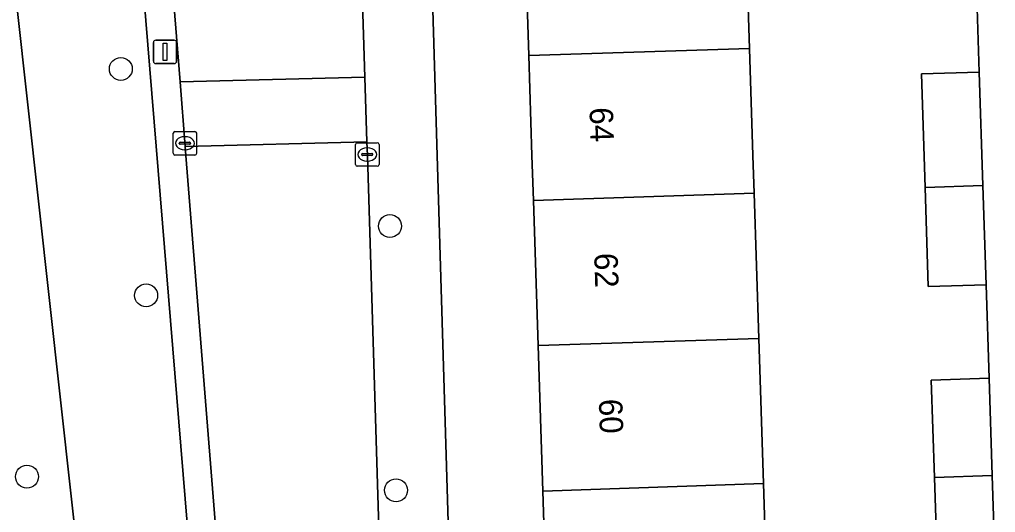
# Model space of a CAD drawing. Extents: x 161248 to 161848, y 384871 to 385383.
# Drawn here: x 161640.06 to 161681.73, y 385234.77 to 385255.81 of the extents above; entities that cross this region are included whole.
import ezdxf

# ---------------------------------------------------------------- set-up
doc = ezdxf.new("R2010")
doc.units = 0
for name, color, linetype in [('IMGEO_Boom', 7, 'Continuous'), ('IMGEO_Erf', 7, 'Continuous'), ('IMGEO_Groenvoorziening', 7, 'Continuous'), ('IMGEO_Hek', 7, 'Continuous'), ('IMGEO_Kolk', 7, 'Continuous'), ('IMGEO_Lichtmast', 7, 'Continuous'), ('IMGEO_Pand', 7, 'Continuous'), ('IMGEO_Pand_nummerreeks', 7, 'Continuous'), ('IMGEO_Rijbaan_lokaal_open', 7, 'Continuous'), ('IMGEO_Voetpad_open', 7, 'Continuous')]:
    doc.layers.add(name, color=color, linetype=linetype)

msp = doc.modelspace()

# ---------------------------------------------------------------- linework, layer by layer
at = {"layer": 'IMGEO_Boom'}
for centre in [(161644.385, 385253.703), (161655.874, 385246.993), (161645.466, 385244.033), (161640.378, 385236.297), (161656.134, 385235.715)]:
    msp.add_circle(centre, 0.489, dxfattribs=at)
at = {"layer": 'IMGEO_Erf'}
for points in [[(161656.802, 385286.862), (161657.898, 385250), (161658.405, 385232.944), (161658.424, 385230.801), (161658.419, 385230.719), (161662.363, 385229.226), (161662.601, 385229.367), (161662.398, 385235.674), (161662.198, 385241.893), (161661.999, 385248.082), (161661.937, 385250), (161661.8, 385254.271), (161661.6, 385260.469)], [(161671.021, 385260.764), (161671.22, 385254.567), (161671.367, 385250), (161671.419, 385248.399), (161671.618, 385242.191), (161671.817, 385236.003), (161672.021, 385229.67), (161672.019, 385227.661), (161679.034, 385225.151), (161681.726, 385232.005), (161679.258, 385231.926), (161679.119, 385236.258), (161678.986, 385240.421), (161681.454, 385240.5), (161681.326, 385244.488), (161678.858, 385244.409), (161678.722, 385248.645), (161678.566, 385253.489), (161681.034, 385253.568), (161680.931, 385256.771)]]:
    msp.add_lwpolyline(points, dxfattribs=at)
at = {"layer": 'IMGEO_Groenvoorziening'}
msp.add_lwpolyline([(161634.818, 385302.549), (161631.444, 385297.261), (161638.695, 385232.47), (161638.529, 385232.454), (161638.601, 385232.02), (161640.502, 385232.113), (161641.893, 385221.599), (161643.668, 385222.865)], close=True, dxfattribs=at)
for points in [[(161634.818, 385302.549), (161643.668, 385222.865), (161646.836, 385225.698)], [(161647.219, 385234.309), (161642.53, 385291.257), (161641.615, 385301.67)]]:
    msp.add_lwpolyline(points, dxfattribs=at)
at = {"layer": 'IMGEO_Hek'}
msp.add_lwpolyline([(161634.818, 385302.549), (161643.668, 385222.865)], dxfattribs=at)
at = {"layer": 'IMGEO_Kolk'}
for p, q in [((161646.623, 385250.101), (161646.623, 385250.953)), ((161646.698, 385251.027), (161647.55, 385251.027)), ((161647.111, 385250.807), (161647.136, 385250.807)), ((161647.624, 385250.953), (161647.624, 385250.101)), ((161646.882, 385250.521), (161646.882, 385250.533)), ((161647.32, 385250.484), (161646.922, 385250.484)), ((161646.925, 385250.57), (161647.323, 385250.57)), ((161647.366, 385250.533), (161647.366, 385250.521)), ((161654.408, 385249.623), (161654.408, 385250.475)), ((161654.483, 385250.549), (161655.335, 385250.549)), ((161655.409, 385250.475), (161655.409, 385249.623)), ((161647.55, 385250.027), (161646.698, 385250.027)), ((161647.134, 385250.247), (161647.109, 385250.247)), ((161654.667, 385250.043), (161654.667, 385250.055)), ((161655.105, 385250.006), (161654.707, 385250.006)), ((161654.71, 385250.092), (161655.108, 385250.092)), ((161654.896, 385250.329), (161654.921, 385250.329)), ((161655.151, 385250.055), (161655.151, 385250.043)), ((161655.335, 385249.549), (161654.483, 385249.549)), ((161654.919, 385249.769), (161654.894, 385249.769))]:
    msp.add_line(p, q, dxfattribs=at)
for points in [[(161646.623, 385250.101), (161646.623, 385250.953)], [(161646.698, 385251.027), (161647.55, 385251.027)], [(161647.624, 385250.953), (161647.624, 385250.101)], [(161654.408, 385249.623), (161654.408, 385250.475)], [(161654.483, 385250.549), (161655.335, 385250.549)], [(161655.409, 385250.475), (161655.409, 385249.623)], [(161647.55, 385250.027), (161646.698, 385250.027)], [(161655.335, 385249.549), (161654.483, 385249.549)]]:
    msp.add_lwpolyline(points, dxfattribs=at)
for centre, radius, start, end in [((161646.7, 385250.951), 0.0765, 91.552, 178.448), ((161646.7, 385250.951), 0.0765, 91.552, 178.448), ((161647.548, 385250.951), 0.0765, 1.552, 88.448), ((161647.548, 385250.951), 0.0765, 1.552, 88.448), ((161646.922, 385250.53), 0.0403, 85.8775, 175.7526), ((161646.919, 385250.52), 0.0366, 178.938, 274.7102), ((161647.323, 385250.527), 0.043, 264.8664, 352.4533), ((161647.327, 385250.532), 0.0386, 1.7309, 96.639), ((161654.485, 385250.473), 0.0765, 91.552, 178.448), ((161654.485, 385250.473), 0.0765, 91.552, 178.448), ((161655.333, 385250.473), 0.0765, 1.552, 88.448), ((161655.333, 385250.473), 0.0765, 1.552, 88.448), ((161646.7, 385250.103), 0.0765, 181.552, 268.448), ((161646.7, 385250.103), 0.0765, 181.552, 268.448), ((161647.548, 385250.103), 0.0765, 271.552, 358.448), ((161647.548, 385250.103), 0.0765, 271.552, 358.448), ((161654.707, 385250.052), 0.0403, 85.8775, 175.7526), ((161654.704, 385250.042), 0.0366, 178.938, 274.7102), ((161655.108, 385250.049), 0.043, 264.8664, 352.4533), ((161655.112, 385250.054), 0.0386, 1.7309, 96.639), ((161654.485, 385249.625), 0.0765, 181.552, 268.448), ((161654.485, 385249.625), 0.0765, 181.552, 268.448), ((161655.333, 385249.625), 0.0765, 271.552, 358.448), ((161655.333, 385249.625), 0.0765, 271.552, 358.448)]:
    msp.add_arc(centre, radius, start, end, dxfattribs=at)
for centre, major_axis, ratio, start_param, end_param in [((161647.11, 385250.527), (-0.387, 0.002), 0.722429, 4.712389, 7.853982), ((161647.135, 385250.527), (-0.39, 0.002), 0.717154, 1.570796, 4.712389), ((161654.895, 385250.049), (-0.387, 0.002), 0.722429, 4.712389, 7.853982), ((161654.92, 385250.049), (-0.39, 0.002), 0.717154, 1.570796, 4.712389)]:
    msp.add_ellipse(centre, major_axis=major_axis, ratio=ratio, start_param=start_param, end_param=end_param, dxfattribs=at)
at = {"layer": 'IMGEO_Lichtmast'}
for p, q in [((161645.875, 385254.93), (161646.665, 385254.93)), ((161646.665, 385254.93), (161645.875, 385254.93)), ((161645.775, 385254.03), (161645.775, 385254.83)), ((161645.775, 385254.83), (161645.775, 385254.03)), ((161646.765, 385254.83), (161646.765, 385254.03)), ((161646.765, 385254.03), (161646.765, 385254.83)), ((161646.665, 385253.93), (161645.875, 385253.93)), ((161645.875, 385253.93), (161646.665, 385253.93))]:
    msp.add_line(p, q, dxfattribs=at)
msp.add_lwpolyline([(161646.195, 385254.805), (161646.345, 385254.805), (161646.345, 385254.055), (161646.195, 385254.055), (161646.195, 385254.805)], dxfattribs=at)
for centre, start, end in [((161645.875, 385254.83), 90, 180), ((161645.875, 385254.83), 90, 180), ((161646.665, 385254.83), 0, 90), ((161646.665, 385254.83), 360, 90), ((161645.875, 385254.03), 180, 270), ((161645.875, 385254.03), 180, 270), ((161646.665, 385254.03), 270, 0), ((161646.665, 385254.03), 270, 0)]:
    msp.add_arc(centre, 0.1, start, end, dxfattribs=at)
at = {"layer": 'IMGEO_Pand'}
for points in [[(161671.22, 385254.567), (161671.021, 385260.764), (161661.6, 385260.469), (161661.8, 385254.271)], [(161661.8, 385254.271), (161661.937, 385250), (161661.999, 385248.082), (161671.419, 385248.399), (161671.367, 385250), (161671.22, 385254.567)], [(161681.034, 385253.568), (161678.566, 385253.489), (161678.722, 385248.645), (161681.189, 385248.728)], [(161681.189, 385248.728), (161678.722, 385248.645), (161678.858, 385244.409), (161681.326, 385244.488)], [(161671.618, 385242.191), (161671.419, 385248.399), (161661.999, 385248.082), (161662.198, 385241.893)], [(161671.817, 385236.003), (161671.618, 385242.191), (161662.198, 385241.893), (161662.398, 385235.674)], [(161681.454, 385240.5), (161678.986, 385240.421), (161679.119, 385236.258), (161681.587, 385236.344)], [(161681.587, 385236.344), (161679.119, 385236.258), (161679.258, 385231.926), (161681.726, 385232.005)], [(161662.398, 385235.674), (161662.601, 385229.367), (161667.599, 385229.528), (161672.021, 385229.67), (161671.817, 385236.003)]]:
    msp.add_lwpolyline(points, close=True, dxfattribs=at)
at = {"layer": 'IMGEO_Rijbaan_lokaal_open'}
for points in [[(161654.806, 385253.352), (161653.796, 385285.454), (161653.587, 385292.097), (161653.094, 385307.768), (161642.53, 385307.436), (161642.986, 385301.793), (161646.913, 385253.15)], [(161647.135, 385250.394), (161654.892, 385250.594), (161654.806, 385253.352), (161646.913, 385253.15)]]:
    msp.add_lwpolyline(points, close=True, dxfattribs=at)
msp.add_lwpolyline([(161646.477, 385219.731), (161642.948, 385210.8), (161635.004, 385190.489), (161641.438, 385187.982), (161648.956, 385207.28), (161652.424, 385216.415), (161653.708, 385220.298), (161654.641, 385224.281), (161655.214, 385228.331), (161655.423, 385232.416), (161655.402, 385234.118), (161654.91, 385250), (161654.892, 385250.594), (161647.135, 385250.394), (161647.167, 385250), (161648.501, 385233.307)], dxfattribs=at)
at = {"layer": 'IMGEO_Voetpad_open'}
for points in [[(161648.501, 385233.307), (161647.167, 385250), (161647.135, 385250.394), (161646.913, 385253.15), (161642.986, 385301.793), (161641.938, 385301.699), (161641.615, 385301.67), (161642.53, 385291.257), (161647.219, 385234.309)], [(161642.519, 385182.649), (161655.412, 385215.533), (161656.675, 385219.233), (161657.602, 385223.032), (161658.187, 385226.898), (161658.366, 385229.85), (161658.419, 385230.719), (161658.424, 385230.801), (161658.405, 385232.944), (161657.898, 385250), (161656.802, 385286.862)], [(161653.796, 385285.454), (161654.806, 385253.352), (161654.892, 385250.594), (161654.91, 385250), (161655.402, 385234.118), (161655.423, 385232.416), (161655.214, 385228.331), (161654.641, 385224.281), (161653.708, 385220.298), (161652.424, 385216.415), (161648.956, 385207.28), (161641.438, 385187.982)], [(161680.931, 385256.771), (161681.034, 385253.568), (161681.189, 385248.728), (161681.326, 385244.488), (161681.454, 385240.5), (161681.587, 385236.344), (161681.726, 385232.005)]]:
    msp.add_lwpolyline(points, dxfattribs=at)

# ---------------------------------------------------------------- texts
at = {"layer": 'IMGEO_Pand_nummerreeks'}
for s, p in [('64', (161664.393, 385252.051)), ('62', (161664.593, 385245.832)), ('60', (161664.793, 385239.604))]:
    msp.add_text(s, height=1, rotation=271.8432, dxfattribs=at).set_placement(p)

doc.saveas('drawing.dxf')
